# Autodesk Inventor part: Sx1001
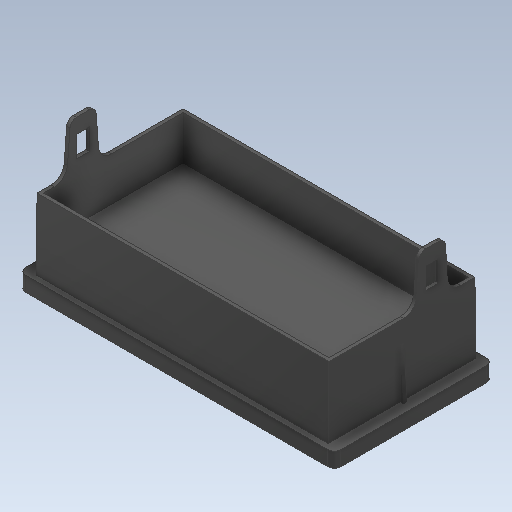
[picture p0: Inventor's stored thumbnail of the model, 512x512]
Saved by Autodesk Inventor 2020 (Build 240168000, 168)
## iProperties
Created: 2021-02
Part Number: Sx1001
Material: Generico
Document SubType Name: Modeling
Designer: zambolin
Density: 1 g/cm^3
Appearance: Default
Author: zambolin
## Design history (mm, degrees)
feature "Solido2"
node "Solido1"
